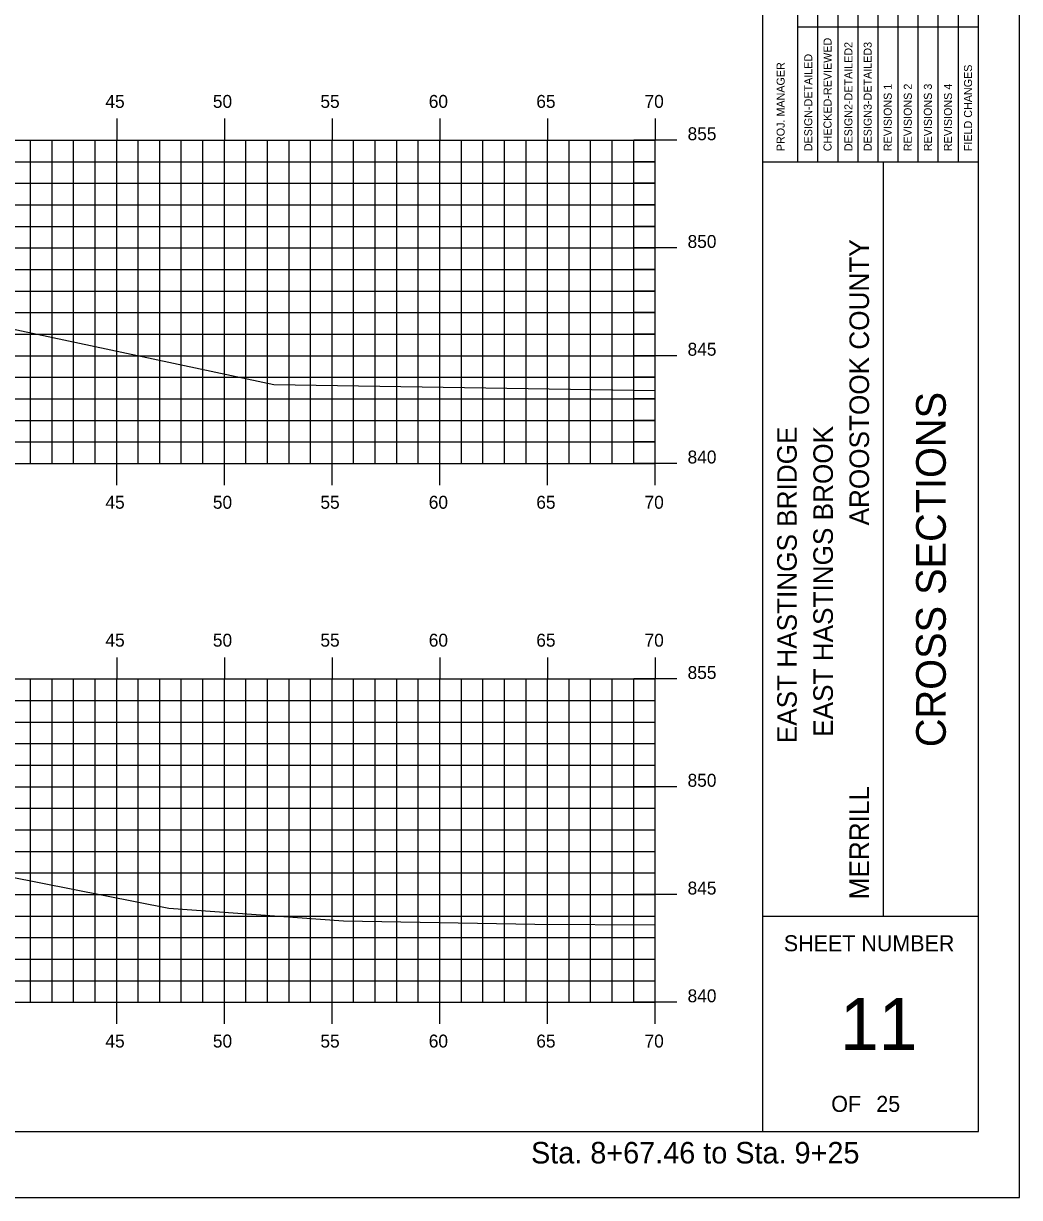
# Model space of a CAD drawing. Extents: x 2194502 to 2194968, y 863888 to 863998.
# Drawn here: x 2194739.2 to 2194785.4, y 863888.4 to 863942.9 of the extents above; entities that cross this region are included whole.
import ezdxf

# ---------------------------------------------------------------- set-up
doc = ezdxf.new("R2010")
doc.units = 0
for name, color, linetype in [('BORDER', 7, 'Continuous'), ('BRIDGE_TITLE', 7, 'Continuous'), ('H_V ANNOTATION', 7, 'Continuous'), ('MAJOR', 7, 'Continuous'), ('MINOR', 7, 'Continuous'), ('PLOT BOUNDARY', 7, 'Continuous'), ('S_Roadway_Centerline', 7, 'Continuous')]:
    doc.layers.add(name, color=color, linetype=linetype)

msp = doc.modelspace()

# ---------------------------------------------------------------- linework, layer by layer
at = {"layer": 'BORDER'}
for p, q in [((2194773.499, 863891.446), (2194773.499, 863996.446)), ((2194773.499, 863936.449), (2194783.499, 863936.449)), ((2194779.091, 863901.449), (2194779.091, 863936.449)), ((2194773.499, 863901.449), (2194783.499, 863901.449))]:
    msp.add_line(p, q, dxfattribs=at)
msp.add_lwpolyline([(2194623.499, 863891.446), (2194783.499, 863891.446), (2194783.499, 863996.446), (2194623.499, 863996.446)], close=True, dxfattribs=at)
for points in [[(2194776.047, 863936.452), (2194776.047, 863953.949)], [(2194776.979, 863953.949), (2194776.979, 863936.452)], [(2194777.91, 863936.452), (2194777.91, 863953.949)], [(2194778.842, 863936.452), (2194778.842, 863953.949)], [(2194779.774, 863936.452), (2194779.774, 863953.949)], [(2194780.705, 863936.452), (2194780.705, 863953.949)], [(2194781.637, 863936.452), (2194781.637, 863953.949)], [(2194782.569, 863936.452), (2194782.569, 863953.949)], [(2194775.115, 863936.452), (2194775.115, 863953.243)], [(2194775.114, 863942.699), (2194783.499, 863942.699)]]:
    msp.add_lwpolyline(points, dxfattribs=at)
at = {"layer": 'MAJOR'}
for p, q in [((2194743.499, 863938.448), (2194743.499, 863937.446)), ((2194748.499, 863938.448), (2194748.499, 863937.446)), ((2194753.499, 863938.448), (2194753.499, 863937.446)), ((2194758.499, 863938.448), (2194758.499, 863937.446)), ((2194763.499, 863938.448), (2194763.499, 863937.446)), ((2194768.499, 863938.448), (2194768.499, 863937.446)), ((2194628.499, 863937.446), (2194768.499, 863937.446)), ((2194743.499, 863922.446), (2194743.499, 863937.446)), ((2194748.499, 863922.446), (2194748.499, 863937.446)), ((2194753.499, 863922.446), (2194753.499, 863937.446)), ((2194758.499, 863922.446), (2194758.499, 863937.446)), ((2194763.499, 863922.446), (2194763.499, 863937.446)), ((2194769.501, 863937.446), (2194767.497, 863937.446)), ((2194768.499, 863922.446), (2194768.499, 863937.446)), ((2194768.499, 863922.446), (2194768.499, 863937.446)), ((2194628.499, 863932.446), (2194768.499, 863932.446)), ((2194769.501, 863932.446), (2194767.497, 863932.446)), ((2194628.499, 863927.446), (2194768.499, 863927.446)), ((2194769.501, 863927.446), (2194767.497, 863927.446)), ((2194628.499, 863922.446), (2194768.499, 863922.446)), ((2194743.499, 863921.444), (2194743.499, 863922.446)), ((2194748.499, 863921.444), (2194748.499, 863922.446)), ((2194753.499, 863921.444), (2194753.499, 863922.446)), ((2194758.499, 863921.444), (2194758.499, 863922.446)), ((2194763.499, 863921.444), (2194763.499, 863922.446)), ((2194769.501, 863922.446), (2194767.497, 863922.446)), ((2194768.499, 863921.444), (2194768.499, 863922.446)), ((2194743.499, 863913.448), (2194743.499, 863912.446)), ((2194748.499, 863913.448), (2194748.499, 863912.446)), ((2194753.499, 863913.448), (2194753.499, 863912.446)), ((2194758.499, 863913.448), (2194758.499, 863912.446)), ((2194763.499, 863913.448), (2194763.499, 863912.446)), ((2194768.499, 863913.448), (2194768.499, 863912.446)), ((2194628.499, 863912.446), (2194768.499, 863912.446)), ((2194743.499, 863897.446), (2194743.499, 863912.446)), ((2194748.499, 863897.446), (2194748.499, 863912.446)), ((2194753.499, 863897.446), (2194753.499, 863912.446)), ((2194758.499, 863897.446), (2194758.499, 863912.446)), ((2194763.499, 863897.446), (2194763.499, 863912.446)), ((2194769.501, 863912.446), (2194767.497, 863912.446)), ((2194768.499, 863897.446), (2194768.499, 863912.446)), ((2194768.499, 863897.446), (2194768.499, 863912.446)), ((2194628.499, 863907.446), (2194768.499, 863907.446)), ((2194769.501, 863907.446), (2194767.497, 863907.446)), ((2194628.499, 863902.446), (2194768.499, 863902.446)), ((2194769.501, 863902.446), (2194767.497, 863902.446)), ((2194628.499, 863897.446), (2194768.499, 863897.446)), ((2194743.499, 863896.444), (2194743.499, 863897.446)), ((2194748.499, 863896.444), (2194748.499, 863897.446)), ((2194753.499, 863896.444), (2194753.499, 863897.446)), ((2194758.499, 863896.444), (2194758.499, 863897.446)), ((2194763.499, 863896.444), (2194763.499, 863897.446)), ((2194769.501, 863897.446), (2194767.497, 863897.446)), ((2194768.499, 863896.444), (2194768.499, 863897.446))]:
    msp.add_line(p, q, dxfattribs=at)
at = {"layer": 'MINOR'}
for p, q in [((2194739.499, 863922.446), (2194739.499, 863937.446)), ((2194740.499, 863922.446), (2194740.499, 863937.446)), ((2194741.499, 863922.446), (2194741.499, 863937.446)), ((2194742.499, 863922.446), (2194742.499, 863937.446)), ((2194744.499, 863922.446), (2194744.499, 863937.446)), ((2194745.499, 863922.446), (2194745.499, 863937.446)), ((2194746.499, 863922.446), (2194746.499, 863937.446)), ((2194747.499, 863922.446), (2194747.499, 863937.446)), ((2194749.499, 863922.446), (2194749.499, 863937.446)), ((2194750.499, 863922.446), (2194750.499, 863937.446)), ((2194751.499, 863922.446), (2194751.499, 863937.446)), ((2194752.499, 863922.446), (2194752.499, 863937.446)), ((2194754.499, 863922.446), (2194754.499, 863937.446)), ((2194755.499, 863922.446), (2194755.499, 863937.446)), ((2194756.499, 863922.446), (2194756.499, 863937.446)), ((2194757.499, 863922.446), (2194757.499, 863937.446)), ((2194759.499, 863922.446), (2194759.499, 863937.446)), ((2194760.499, 863922.446), (2194760.499, 863937.446)), ((2194761.499, 863922.446), (2194761.499, 863937.446)), ((2194762.499, 863922.446), (2194762.499, 863937.446)), ((2194764.499, 863922.446), (2194764.499, 863937.446)), ((2194765.499, 863922.446), (2194765.499, 863937.446)), ((2194766.499, 863922.446), (2194766.499, 863937.446)), ((2194767.499, 863922.446), (2194767.499, 863937.446)), ((2194628.499, 863936.446), (2194768.499, 863936.446)), ((2194768.499, 863936.446), (2194767.497, 863936.446)), ((2194628.499, 863935.446), (2194768.499, 863935.446)), ((2194768.499, 863935.446), (2194767.497, 863935.446)), ((2194628.499, 863934.446), (2194768.499, 863934.446)), ((2194768.499, 863934.446), (2194767.497, 863934.446)), ((2194628.499, 863933.446), (2194768.499, 863933.446)), ((2194768.499, 863933.446), (2194767.497, 863933.446)), ((2194628.499, 863931.446), (2194768.499, 863931.446)), ((2194768.499, 863931.446), (2194767.497, 863931.446)), ((2194628.499, 863930.446), (2194768.499, 863930.446)), ((2194768.499, 863930.446), (2194767.497, 863930.446)), ((2194628.499, 863929.446), (2194768.499, 863929.446)), ((2194768.499, 863929.446), (2194767.497, 863929.446)), ((2194628.499, 863928.446), (2194768.499, 863928.446)), ((2194768.499, 863928.446), (2194767.497, 863928.446)), ((2194628.499, 863926.446), (2194768.499, 863926.446)), ((2194768.499, 863926.446), (2194767.497, 863926.446)), ((2194628.499, 863925.446), (2194768.499, 863925.446)), ((2194768.499, 863925.446), (2194767.497, 863925.446)), ((2194628.499, 863924.446), (2194768.499, 863924.446)), ((2194768.499, 863924.446), (2194767.497, 863924.446)), ((2194628.499, 863923.446), (2194768.499, 863923.446)), ((2194768.499, 863923.446), (2194767.497, 863923.446)), ((2194739.499, 863897.446), (2194739.499, 863912.446)), ((2194740.499, 863897.446), (2194740.499, 863912.446)), ((2194741.499, 863897.446), (2194741.499, 863912.446)), ((2194742.499, 863897.446), (2194742.499, 863912.446)), ((2194744.499, 863897.446), (2194744.499, 863912.446)), ((2194745.499, 863897.446), (2194745.499, 863912.446)), ((2194746.499, 863897.446), (2194746.499, 863912.446)), ((2194747.499, 863897.446), (2194747.499, 863912.446)), ((2194749.499, 863897.446), (2194749.499, 863912.446)), ((2194750.499, 863897.446), (2194750.499, 863912.446)), ((2194751.499, 863897.446), (2194751.499, 863912.446)), ((2194752.499, 863897.446), (2194752.499, 863912.446)), ((2194754.499, 863897.446), (2194754.499, 863912.446)), ((2194755.499, 863897.446), (2194755.499, 863912.446)), ((2194756.499, 863897.446), (2194756.499, 863912.446)), ((2194757.499, 863897.446), (2194757.499, 863912.446)), ((2194759.499, 863897.446), (2194759.499, 863912.446)), ((2194760.499, 863897.446), (2194760.499, 863912.446)), ((2194761.499, 863897.446), (2194761.499, 863912.446)), ((2194762.499, 863897.446), (2194762.499, 863912.446)), ((2194764.499, 863897.446), (2194764.499, 863912.446)), ((2194765.499, 863897.446), (2194765.499, 863912.446)), ((2194766.499, 863897.446), (2194766.499, 863912.446)), ((2194767.499, 863897.446), (2194767.499, 863912.446)), ((2194628.499, 863911.446), (2194768.499, 863911.446)), ((2194628.499, 863910.446), (2194768.499, 863910.446)), ((2194628.499, 863909.446), (2194768.499, 863909.446)), ((2194628.499, 863908.446), (2194768.499, 863908.446)), ((2194628.499, 863906.446), (2194768.499, 863906.446)), ((2194628.499, 863905.446), (2194768.499, 863905.446)), ((2194628.499, 863904.446), (2194768.499, 863904.446)), ((2194628.499, 863903.446), (2194768.499, 863903.446)), ((2194628.499, 863901.446), (2194768.499, 863901.446)), ((2194628.499, 863900.446), (2194768.499, 863900.446)), ((2194628.499, 863899.446), (2194768.499, 863899.446)), ((2194628.499, 863898.446), (2194768.499, 863898.446))]:
    msp.add_line(p, q, dxfattribs=at)
at = {"layer": 'PLOT BOUNDARY'}
msp.add_lwpolyline([(2194615.406, 863888.387), (2194785.406, 863888.387), (2194785.406, 863998.387), (2194615.406, 863998.387)], close=True, dxfattribs=at)
at = {"layer": 'S_Roadway_Centerline'}
for points in [[(2194628.499, 863931.248), (2194644.102, 863931.812), (2194651.913, 863930.949), (2194668.077, 863929.672), (2194681.104, 863932.691), (2194681.74, 863932.878), (2194687.144, 863933.179), (2194687.162, 863933.181), (2194691.811, 863933.191), (2194698.499, 863933.212), (2194698.585, 863933.211), (2194710.18, 863932.915), (2194712.278, 863932.755), (2194712.76, 863932.719), (2194712.774, 863932.719), (2194718.053, 863932.454), (2194719.251, 863932.444), (2194722.99, 863932.169), (2194730.529, 863930.489), (2194735.351, 863929.559), (2194737.618, 863928.913), (2194750.8, 863926.104), (2194768.499, 863925.832)], [(2194667.598, 863903.809), (2194672.818, 863905.013), (2194682.058, 863907.726), (2194686.684, 863907.983), (2194687.208, 863908.025), (2194696.988, 863908.045), (2194698.48, 863908.066), (2194700.167, 863908.027), (2194710.222, 863907.77), (2194710.933, 863907.72), (2194713.063, 863907.563), (2194714.672, 863907.54), (2194718.844, 863907.33), (2194723.196, 863907.293), (2194725.536, 863907.121), (2194734.215, 863905.192), (2194736.558, 863903.65), (2194738.492, 863903.278), (2194745.923, 863901.819), (2194754.026, 863901.226), (2194762.901, 863901.073), (2194768.499, 863901.043)]]:
    msp.add_lwpolyline(points, dxfattribs=at)

# ---------------------------------------------------------------- texts
at = {"layer": 'BORDER'}
for s, height, rotation, p in [('CHECKED-REVIEWED', 0.37275, 90, (2194776.681, 863936.937)), ('DESIGN2-DETAILED2', 0.37275, 90, (2194777.649, 863936.937)), ('DESIGN3-DETAILED3', 0.37275, 90, (2194778.544, 863936.937)), ('DESIGN-DETAILED', 0.37275, 90, (2194775.786, 863936.937)), ('PROJ. MANAGER', 0.37275, 90, (2194774.504, 863936.937)), ('FIELD CHANGES', 0.37275, 90, (2194783.202, 863936.937)), ('REVISIONS 1', 0.37275, 90, (2194779.476, 863936.937)), ('REVISIONS 2', 0.37275, 90, (2194780.407, 863936.937)), ('REVISIONS 3', 0.37275, 90, (2194781.339, 863936.937)), ('REVISIONS 4', 0.37275, 90, (2194782.271, 863936.937)), ('CROSS SECTIONS', 1.37787, 90, (2194781.984, 863909.283)), ('SHEET NUMBER', 0.74527, 360, (2194774.465, 863899.812)), ('11', 2.4194, 360, (2194777.067, 863895.228)), ('OF', 0.7453, 360, (2194776.666, 863892.359)), ('25', 0.7453, 360, (2194778.756, 863892.359))]:
    msp.add_text(s, height=height, rotation=rotation, dxfattribs=at).set_placement(p)
at = {"layer": 'BRIDGE_TITLE'}
for s, height, p in [('AROOSTOOK COUNTY', 0.90716, (2194778.42, 863919.571)), ('EAST HASTINGS BRIDGE', 0.90716, (2194775.066, 863909.466)), ('EAST HASTINGS BROOK', 0.90716, (2194776.743, 863909.763)), ('MERRILL', 0.9072, (2194778.42, 863902.222))]:
    msp.add_text(s, height=height, rotation=90, dxfattribs=at).set_placement(p)
at = {"layer": 'H_V ANNOTATION'}
for s, height, p in [('45', 0.6, (2194742.977, 863938.946)), ('50', 0.6, (2194747.964, 863938.946)), ('55', 0.6, (2194752.956, 863938.946)), ('60', 0.6, (2194757.985, 863938.946)), ('65', 0.6, (2194762.977, 863938.946)), ('70', 0.6, (2194768.001, 863938.946)), ('855', 0.6, (2194769.999, 863937.446)), ('850', 0.6, (2194769.999, 863932.446)), ('845', 0.6, (2194769.999, 863927.446)), ('840', 0.6, (2194769.999, 863922.446)), ('45', 0.6, (2194742.977, 863920.346)), ('50', 0.6, (2194747.964, 863920.346)), ('55', 0.6, (2194752.956, 863920.346)), ('60', 0.6, (2194757.985, 863920.346)), ('65', 0.6, (2194762.977, 863920.346)), ('70', 0.6, (2194768.001, 863920.346)), ('45', 0.6, (2194742.977, 863913.946)), ('50', 0.6, (2194747.964, 863913.946)), ('55', 0.6, (2194752.956, 863913.946)), ('60', 0.6, (2194757.985, 863913.946)), ('65', 0.6, (2194762.977, 863913.946)), ('70', 0.6, (2194768.001, 863913.946)), ('855', 0.6, (2194769.999, 863912.446)), ('850', 0.6, (2194769.999, 863907.446)), ('845', 0.6, (2194769.999, 863902.446)), ('840', 0.6, (2194769.999, 863897.446)), ('45', 0.6, (2194742.977, 863895.346)), ('50', 0.6, (2194747.964, 863895.346)), ('55', 0.6, (2194752.956, 863895.346)), ('60', 0.6, (2194757.985, 863895.346)), ('65', 0.6, (2194762.977, 863895.346)), ('70', 0.6, (2194768.001, 863895.346)), ('Sta. 8+67.46 to Sta. 9+25', 1.0002, (2194762.732, 863889.966))]:
    msp.add_text(s, height=height, dxfattribs=at).set_placement(p)

doc.saveas('drawing.dxf')
